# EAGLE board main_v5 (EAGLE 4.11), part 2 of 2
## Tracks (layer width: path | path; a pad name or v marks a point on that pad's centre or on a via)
+5V  (via drill 0.61)
  Top 0.61: IC501.16 144.14,18.89 145.41,20.16 145.41,25.87 149.22,29.68 149.22,33.49 149.85,34.12 IC501.9 | 97.15,52.54 IC402.16 104.77,52.54 106.36,50.95 115.25,50.95 116.83,52.54 IC403.16 | IC301.14 146.68,133.19 153.03,139.53 153.03,143.34 | 153.03,143.34 153.03,147.16 154.3,148.42 R304.2 | 153.03,143.34 R305.2 | Q802.3 168.91,32.7 168.91,27.93 Q801.3
  Top 0.813: C306.1 100.32,121.76 97.15,117.95 97.15,52.54 v97.15,35.08
  Bottom 0.61: IC501.16 C508.1 R501.2 139.69,22.7 140.97,23.96 140.97,27.14 141.6,27.78 144.78,27.78 145.41,28.41 145.41,29.68 144.78,30.32 138.42,30.32 137.79,29.68 137.79,24.6 136.52,23.33 136.52,18.25 135.25,16.98 135.25,10.63 133.98,9.36 C506.1 130.17,10 116.44,10 114.3,12.22 114.3,25.87 113.02,27.14 111.12,27.14 109.85,28.41 IC51.6 | R402.2 128.9,42.38 130.17,43.65 130.17,50.25 | 130.17,50.25 R401.1 132.07,53.17 132.07,68.42 130.81,69.69 130.81,75.4 132.07,76.67 132.07,78.58 130.17,80.48 114.93,80.48 114.3,81.12 IC401.14 | 130.17,50.25 123.82,50.25 122.55,51.27 122.55,57.62 121.28,58.89 116.83,58.89 116.2,58.25 116.2,53.17 116.83,52.54 IC403.16 | 152.39,34.12 152.32,34.12 | 152.39,34.12 154.3,34.12 158.27,30.16 167,30.16 168.91,32.06 168.91,32.85 Q802.3 | IC501.9 152.39,34.12
  Bottom 0.813: C703.1 IC702.OUT | 90.8,33.49 R701.2 31.27,33.49 28.57,30.79 C703.1 | 90.8,33.49 95.56,33.49 v97.15,35.08 107.94,35.08 109.85,32.22 IC51.6 | 90.8,33.49 IC1.6 | 103.5,122.39 103.5,122.87 107.31,126.84 120.01,126.84 126.36,120.48 C301.1 134.93,120.48 136.49,122.04 142.84,122.04 144.14,123.34 IC301.4 | IC301.4 144.14,124.45 | IC301.4 144.14,126.2 146.68,128.74 IC301.14 | C704.1 22.22,23.96 24.76,26.5 C703.1 | 103.5,122.39 | 103.5,122.39 C306.1
+15V  (via drill 2.54)
  Bottom 1.016: IC701.IN 60.32,18.89 59.05,17.62 10.79,17.62 8.25,20.16 8.25,21.43 | 8.25,21.43 8.25,31.59 12.06,35.39 94.61,35.39 97.15,37.93 170.81,37.93 176.53,43.65 L601.1 | v5.71,21.43 8.25,21.43
GND  (via drill 0.25 pad 12.7, 0.61, 2.54)
  Top 0.61: 37.46,150.97 VR251.2 36.19,139.53 36.19,116.67 | 12.06,150.97 VR201.2 10.79,139.53 10.79,116.67 | 10.79,116.67 VR202.2 | 10.79,116.67 10.79,106.52 | 10.79,106.52 VR202.3 | 10.79,106.52 R208.1 | 36.19,116.67 36.83,116.67 36.83,106.52 | 36.83,106.52 VR252.3 | 36.83,106.52 36.83,103.34 R258.1 36.83,102.07 36.83,90.32 | 36.19,116.67 VR252.2 | C255.2 C256.2 | C205.2 C206.2 | 36.83,90.32 34.29,90.32 33.02,89.05 33.02,72.86 31.11,70.95 | CON1.6 CON1.5 | 97.15,23.33 R1.1 | IC1.3 IC1.4 | 31.11,70.95 C208.2 | C208.2 C210.2 26.98,56.35 26.98,51.27 28.89,49.36 R218.1 | C208.2 32.38,60.79 34.92,58.25 C261.2 44.13,52.86 47.3,52.86 | C258.2 C260.2 52.7,55.71 52.7,49.36 | 52.7,49.36 R268.1 | 52.7,49.36 52.7,50.16 52.54,50.32 49.84,50.32 47.3,52.86 | 140.63,88.73 arc-45 141.2,88.5 141.6,88.1 | 141.6,88.1 C405.2 | C406.2 141.2,93.42 arc45 140.97,92.84 140.97,88.73 141.6,88.1 | 116.2,23.33 R51.1 | 36.83,90.32 IC203.GND | v82.23,30 82.23,33.81 83.5,35.08 v83.5,38.25 80.64,38.25 | 65.4,87.47 IC253.GND | IC201.4 28.57,73.5 31.11,70.95 | C224.2 13.97,56.35 C211.2 | 47.3,52.86 46.98,52.86 C274.2 | C53.2 123.19,23.33 | 123.19,19.52 R52.1 | 93.37,1.1 93.37,4.98 | 107.31,1.1 107.31,1.74 | 107.31,1.74 107.31,1.77 | 117.47,1.1 R53.1 | 173.35,17.62 C801.2 | 163.98,34.12 C511.2 | U$8.P$2 165.73,6.19 | C512.2 153.66,36.03 153.66,37.93 | 107.31,1.74 VR51.1 | 128.27,139.53 128.11,139.53 X301.5
  Top 0.813: 207.64,48.09 C616.2 201.92,46.19 194.31,46.19 C617.2 | 207.64,48.09 207.64,39.2 | 207.64,39.2 207.64,25.23 | 207.64,25.23 207.64,21.43 | 207.64,21.43 207.64,17.62 | 207.64,17.62 207.64,13.8 | 207.64,13.8 207.64,1.1 194.94,1.1 | 194.94,1.1 173.35,1.1 | 173.35,1.1 173.35,6.82 | 173.35,6.82 173.35,16.34 | 173.35,29.05 173.35,34.12 | 173.35,29.05 173.35,17.62 173.35,16.34 | 173.35,34.12 173.35,37.93 | 173.35,37.93 173.35,43.01 180.97,43.01 | 180.97,43.01 C619.2 | 173.35,37.93 C614.2 | 173.35,34.12 C613.2 | 173.35,16.34 C615.2 | 173.35,6.82 R604.1 | 194.94,1.1 R602.1 | 207.64,13.8 C601.2 | 207.64,17.62 C602.2 | 207.64,21.43 R603.1 | 207.64,25.23 C604.2 | 203.19,39.2 R608.1 | 207.64,39.2 203.19,39.2 | 203.19,39.2 C607.2 | R609.1 173.35,77.31 173.35,79.84 | 173.35,90.64 173.35,88.42 | 173.35,88.42 173.35,83.66 | 173.35,83.66 173.35,79.84 | 191.13,150.97 190.5,150.97 | 191.13,150.97 207.64,150.97 207.64,93.81 | 207.64,93.81 207.64,83.66 | 207.64,83.66 207.64,81.75 | 207.64,81.75 207.64,77.31 | 207.64,77.31 207.64,48.09 | 207.64,77.31 TR601SEC.2 | 173.35,90.64 C618.2 | 173.35,88.42 T603.2 187.95,88.73 | 173.35,79.84 183.51,79.84 D601.1 207.64,81.75 | 187.95,88.73 187.95,93.81 207.64,93.81 | 187.95,88.73 187.95,83.66 | 207.64,83.66 187.95,83.66 | 187.95,83.66 173.35,83.66 | 163.98,16.34 163.98,18.81 | 163.98,13.8 163.98,16.34 | 163.98,13.8 R502.2 | 163.98,18.81 C509.2 159.47,18.79 157.47,20.79 C510.2 | 163.98,16.34 C507.2 | 163.98,9.36 163.98,10.83 | 163.98,10.83 163.98,13.8 | 142.87,1.1 130.81,1.1 | 153.03,1.1 142.87,1.1 | 160.65,1.1 153.03,1.1 | 130.81,1.1 C506.2 | 125.09,16.98 C501.1 | 125.09,1.1 130.81,1.1 | 125.09,16.98 125.09,18.89 | 125.09,18.89 C508.2 136.52,16.98 140.33,16.98 141.41,18.25 141.41,20.79 142.23,21.43 IC501.15
  Top 0.813: 125.09,18.89 125.09,25.23 | 125.09,25.23 125.09,29.05 | 125.09,29.05 C502.1 | 125.09,25.23 C504.2 | 163.98,9.36 160.65,9.36 CON1.19 CON1.20 160.65,1.1 | 153.03,1.1 CON1.14 CON1.13 | 142.87,1.1 CON1.6 | 173.35,1.1 165.73,1.1 | 165.73,1.1 160.65,1.1 | 173.35,29.05 IC601.GND | 179.7,150.97 191.13,150.97 | 179.7,150.97 179.06,150.97 | 173.35,150.97 173.35,136.99 | 173.35,136.99 173.35,133.19 | 173.35,133.19 173.35,121.76 | 173.35,150.97 179.7,150.97 | 163.19,150.97 173.35,150.97 | 163.19,150.97 163.19,145.88 | 163.19,145.88 163.19,140.8 | 163.19,140.8 163.19,110.96 142.71,110.96 | 163.19,145.88 ZD302.A | 163.19,140.8 ZD301.A | 142.71,110.96 130.17,110.96 | 130.17,110.96 116.2,110.96 | 116.2,110.96 107.31,110.96 | 107.31,110.96 103.5,110.96 C306.2 | 128.11,150.97 104.77,150.97 | 128.11,150.97 163.19,150.97 | 116.2,110.96 L301.1 | 107.31,110.96 C305.1 | VR301.1 104.77,124.3 104.77,150.97 | 123.19,1.1 125.09,1.1 | 123.19,1.1 117.47,1.1 107.31,1.1 93.37,1.1 83.19,1.1 | 80.64,1.1 83.19,1.1 | 80.64,1.1 80,1.1 | C3.2 97.15,23.33 IC1.4 IC1.3 90.8,21.43 90.16,20.79 C5.2 | C3.2 R2.1 | 83.19,1.1 VR1.1 | C3.2 100.96,24.6 102.23,25.87 108.58,25.87 109.85,24.6 IC51.3 | 163.98,18.81 163.98,34.12 163.98,37.93 153.66,37.93 130.25,37.93 130.25,39.84 143.5,39.84 | 163.19,74.13 163.19,109.06 144.14,109.06 | 163.19,61.43 163.19,74.13 | 163.19,53.81 163.19,61.43 | 163.19,53.81 163.19,39.84 143.5,39.84 | 125.09,29.05 125.09,35.39 126.36,35.39 126.36,37.36 98.42,37.36 | 0.63,16.34 v5.71,16.34 | 0.63,16.34 0.63,1.1 76.19,1.1 | 60.32,35.39 76.19,35.39 76.19,19.52 78.1,19.52 78.1,35.39 80.64,35.39 80.64,37.3 | 33.65,35.39 45.08,35.39 | 0.63,35.39 17.77,35.39
  Top 0.813: 17.77,35.39 18.41,35.39 C704.2 | 0.63,35.39 0.63,16.34 | 76.19,1.1 78.1,1.1 | 78.1,1.1 80.64,1.1 | IC702.GND 31.11,23.33 33.65,25.87 C703.2 33.65,35.39 | 45.08,35.39 C701.2 | 0.63,70.32 0.63,58.25 | 0.63,70.32 0.63,150.97 12.06,150.97 27.3,150.97 | 0.63,70.32 C223.2 | 0.63,58.25 C211.2 | 73.02,37.3 61.59,37.3 | 73.02,37.3 73.66,37.3 | 0.63,58.25 0.63,37.3 | 0.63,37.3 0.63,35.39 | 80.64,37.3 73.02,37.3 | 61.59,37.3 C264.2 | 80.64,37.3 80.64,38.25 C222.2 | C266.2 78.1,76.35 IC252.4 78.1,70.95 | 78.1,70.95 C268.2 | C216.2 78.1,53.17 IC202.4 78.1,48.09 | 78.1,48.09 C218.2 | 95.88,85.56 95.88,84.92 | 95.88,85.56 65.4,85.56 65.4,87.47 65.4,93.81 | 65.4,150.97 65.4,93.81 | 104.77,150.97 65.4,150.97 | 144.14,109.06 98.42,109.06 | 98.42,95.72 98.42,90.64 | 98.42,109.06 98.42,95.72 | 65.4,93.81 C273.2 | C272.2 83.5,61.11 87.31,61.11 | 87.31,61.11 95.88,61.11 | IC403.6 IC403.7 IC403.8 125.72,73.5 | R410.1 140.63,88.73 arc-45 141.2,88.5 C405.2 | 144.14,109.06 144.14,99.53 | 144.14,99.53 C406.2 140.97,93.18 140.97,88.73 140.97,84.92 129.53,73.5 125.72,73.5 | IC402.6 IC402.7 IC402.8 110.48,71.59 112.39,73.5 114.3,73.5 | 98.42,90.64 C401.2 | 98.42,95.72 C402.2 | 157.47,53.81 C410.2 | 163.19,53.81 157.47,53.81 | 157.47,53.81 C404.2 | 143.5,39.84 R425.1 | 163.19,74.13 R412.1 | 123.82,73.5 114.3,73.5 | 123.82,73.5 124.12,73.5 | 114.3,73.5 IC401.5 | 144.14,99.53 R422.2 | IC404.4 142.87,65.88 147.31,61.43 163.19,61.43 | 45.08,35.39 54.61,35.39 54.61,37.3 33.65,37.3 | 0.63,37.3 33.65,37.3 | 33.65,37.3 C214.2 33.65,42.06 32.06,43.65 30.47,43.65 29.2,45.24 29.2,49.36 R218.1 | 123.19,1.1 123.19,6.19 125.09,6.19 125.09,1.1 | 125.09,16.98 125.09,10 123.19,10 123.19,19.52 123.19,23.33 123.19,35.39 99.05,35.39 99.05,34.12 98.42,33.49 95.24,33.49 95.24,36.03 95.88,36.66 95.88,37.3 86.99,37.3 86.99,37.93
  Top 0.813: 76.19,1.1 76.19,16.03 78.1,16.03 78.1,1.1 | 125.72,73.5 123.82,73.5 | 98.42,90.64 98.42,54.45 | 61.59,37.3 58.41,37.3 58.41,35.39 60.32,35.39 | IC51.3 IC51.4 116.2,23.33 C53.2 | C55.2 109.21,20.79 109.85,21.43 IC51.3 | 65.4,150.97 52.7,150.97 | 52.7,150.97 37.46,150.97 27.3,150.97 | 27.3,150.97 LEFT.2@2 | 52.7,150.97 RIGHT.2@2 | 17.77,35.39 33.65,35.39 | IC701.GND 57.78,23.33 60.32,25.87 C702.2 60.32,35.39 | 87.31,61.11 87.31,68.1 85.72,69.69 83.18,69.69 81.91,70.95 78.1,70.95 | 86.99,37.93 86.99,44.92 84.45,47.46 82.55,47.46 81.91,48.09 78.1,48.09 | 86.99,37.93 86.99,37.62 | 173.35,121.76 C611.2 | 173.35,121.76 173.35,110.33 | 173.35,110.33 173.35,105.88 | 173.35,133.19 C612.2 | 173.35,105.88 173.35,90.64 | 130.17,110.96 C301.2 | IC301.5 146.68,123.18 145.73,122.23 142.71,122.23 | 142.71,122.23 139.85,122.23 139.22,122.87 | 139.22,122.87 | 139.22,122.87 139.06,123.03 IC301.2 | 142.71,110.96 142.71,122.23 | 128.11,150.97 128.11,139.53 128.11,138.74 122.55,133.19 C302.2 | 163.98,9.36 163.98,6.19 165.73,6.19 165.73,1.1 | 95.88,85.56 95.88,117.95 | 98.42,109.06 98.42,116.67 | K1.6 178.43,63.33 188.59,63.33 188.59,56.98 184.78,53.17 184.78,43.01 180.97,43.01 | C6.2 | 163.98,10.83 C6.2 | 175.76,110.33 175.89,110.33 | 175.76,110.33 C610.2 | 173.35,110.33 175.76,110.33 | 175.89,105.88 C609.- 173.35,105.88 | 182.18,136.99 182.24,136.99 | 182.18,136.99 U$6.P$4 | 173.35,136.99 182.18,136.99
  Bottom 0.61: VR201.2 6.34,136.36 C223.2 6.34,44.92 13.01,38.25 v83.5,38.25 | v82.23,30 82.23,11.76 89.07,4.92 92.09,4.92 R3.1 | IC251.4 53.97,75.4 59.69,80.8 59.69,86.83 60.32,87.47 IC253.GND | C303.2 C302.2 | 150.62,0.85 188.97,0.85 193.29,5.04 194.94,5.04 R602.1
  other vias: 200.4,88.73
  pour Top (isolate 0.61): 0.63,1.1 207.64,1.1 207.64,150.97 0.63,150.97
  pour Bottom (isolate 0.61): 0.63,151.6 207,151.6 207,0.47 0.63,0.47
IC402
  Bottom 0.61: R277.2 73.02,81.12 IC252.7 IC252.6 75.56,82.7 77.46,84.61 93.02,84.61 97.78,79.84 97.78,67.15 100.96,63.97 104.13,63.97 104.77,63.33 104.77,60.79 104.13,60.16 IC402.13 100.32,60.16 100.32,44.92 101.02,43.9 104.2,43.9 107.31,40.86 111.12,40.86 112.01,41.74 112.01,43.08 111.12,44.03 109.79,44.03 108.58,45.24 108.58,51.9 109.21,52.54 | 109.21,52.54 112.39,53.81 112.39,57.4 | 112.39,57.4 IC402.3 | IC402.3 | 112.39,57.4 113.56,57.4 116.3,60.16 IC403.13 121.91,60.16 124.45,57.62 IC403.3 126.99,57.62 127.63,56.98 127.63,53.17 126.99,52.54 IC403.1 | 109.21,52.54 IC402.1
N$1
  Top 0.61: R420.2 146.04,65.24 148.59,62.7 152.39,62.7 153.35,63.97 153.35,65.24 152.39,66.51 151.76,66.51 147.95,70.32 145.41,70.32 144.14,71.59 C405.1
  Bottom 0.61: IC404.3 138.42,67.15 139.06,67.78 145.41,67.78 146.04,67.15 R420.2
N$2
  Bottom 0.61: JP201.2 C201.1
N$3
  Bottom 0.61: C202.1 27.3,136.99 C201.2 R201.2
N$4
  Bottom 0.61: R202.1 R203.1 27.3,130.64 C202.2
N$5
  Bottom 0.61: 28.57,120.48 R204.1 22.22,120.48 T201.2 | 28.57,120.48 R203.2 | 28.57,120.48 C204.1
N$6
  Bottom 0.61: R3.2 88.89,12.54 88.26,13.17 | 88.26,13.17 IC1.2 | VR1.3 88.26,13.17
N$7
  Bottom 0.61: VR203.2 12.06,100.17 19.68,106.52 19.68,109.06 20.95,110.33 23.49,110.33 24.76,109.06 T202.E
N$8
  Bottom 0.61: VR202.1 R205.1
N$9
  Bottom 0.61: C203.1 R204.2
N$10
  Bottom 0.61: C203.2 19.68,123.03 R206.1 T201.3
N$11
  Top 0.61: C206.1 31.11,112.23 29.84,113.5 24.7,113.5 | 24.7,113.5 24.73,114.9 16.38,114.9 15.24,116.04 15.24,125.88 R206.2 | 24.7,113.5 24.76,113.5 C205.1
  Bottom 0.61: R206.2 R205.2 | T202.C 30.47,106.52 31.11,107.15 C206.1
N$12
  Bottom 0.61: R207.1 C204.2
N$13
  Bottom 0.61: 22.22,105.25 22.22,103.98 23.49,102.7 VR204.2 26.03,102.7 27.3,103.98 T202.B | 22.22,105.25 22.22,105.88 | 22.22,105.25 C207.2
N$14
  Top 0.61: VR204.1 28.57,102.7 27.3,101.44 VR204.3 19.68,92.55 17.14,90.01 17.14,74.77 14.6,72.23 VR205.3
N$15
  Bottom 0.61: IC201.5 27.3,82.39 25.71,83.97 25.71,87.78 26.66,88.73 R209.1
N$16
  Bottom 0.61: R210.2 28.57,83.66 R211.1 R212.2 31.11,80.16 30.16,79.21 22.86,79.21 22.22,79.84 IC201.7
N$17
  Bottom 0.61: R211.2 30.47,90.64 24.12,90.64 LED201.A LED202.K 16.5,76.67 25.39,76.67 26.03,76.04 26.03,72.23 27.3,70.95 VR206.1
N$18
  Bottom 0.61: VR206.3 26.03,63.33 R214.1
N$19
  Bottom 0.61: VR205.2 12.06,69.05 13.33,67.78 27.3,67.78 31.11,70.95 R212.1
N$20
  Top 0.61: 22.86,84.92 22.86,88.73 24.76,90.64 27.93,90.64 33.65,96.36 R207.2 | 22.86,84.92 R210.1 | 22.86,84.92 24.76,83.02 IC201.6
N$21
  Bottom 0.61: R213.1 13.33,74.77 VR205.1
N$22
  Bottom 0.61: 19.68,48.09 C213.2 | C212.2 19.68,46.82 19.68,48.09 | 19.68,48.09 R218.2
N$23
  Bottom 0.61: R215.1 33.65,60.79 | 33.65,60.79 R214.2 | 33.65,60.79 C208.1
N$24
  Bottom 0.61: R216.1 29.84,51.9 C209.1 31.11,51.9 R215.2
N$25
  Top 0.61: R216.2 22.22,55.08 23.49,56.35 C210.1 23.49,63.33 26.03,65.88 26.03,70.95 24.76,72.54 IC201.3
N$26
  Bottom 0.61: C211.1 15.87,58.25 12.06,54.45 R217.2 10.79,51.43 9.52,50.16 C212.1
N$27
  Bottom 0.61: C252.2 52.7,130.64 R253.1 R252.1
N$28
  Bottom 0.61: C209.2 20.31,51.9 18.41,53.81 R217.1 18.41,56.98 18.73,57.3 18.73,59.52 15.55,62.7 12.06,62.7 10.16,64.61 10.16,71.59 11.43,72.86 12.7,72.86 13.97,71.59 13.97,69.69 14.6,69.05 17.77,69.05 19.68,70.95 IC201.1 IC201.2
N$29
  Bottom 0.61: 47.62,46.82 R268.2 | 47.62,46.82 C263.2 | C262.2 47.62,46.82
N$30
  Bottom 0.61: R251.2 C251.2 52.7,136.99 C252.1
N$31
  Bottom 0.61: JP251.2 C251.1
N$32
  Bottom 0.61: VR251.3 JP251.1 48.89,131.91 50.16,133.19 53.97,133.19 R251.1
N$33
  Bottom 0.61: VR253.2 38.73,100.17 45.08,106.52 45.08,109.06 46.35,110.33 48.89,110.33 51.43,107.79 T252.E
N$34
  Bottom 0.61: 53.97,120.48 R253.2 | 53.97,120.48 R254.1 47.62,120.48 T251.2 | 53.97,120.48 C254.1
N$35
  Bottom 0.61: C253.1 R254.2
N$36
  Bottom 0.61: C253.2 45.08,123.03 R256.2 T251.3
N$37
  Top 0.61: C256.1 56.51,112.23 55.11,113.59 50.16,113.59 50.16,114.77 | 50.16,114.77 41.67,114.79 40.64,115.84 40.64,125.88 R256.1 | 50.16,114.77 C255.1
  Bottom 0.61: R256.1 R255.2 | C256.1 T252.C
N$38
  Bottom 0.61: VR252.1 R255.1
N$39  (via drill 0.61)
  Top 0.61: v83.5,31.27 83.5,33.49 84.77,34.76 v84.77,39.52
  Bottom 0.61: VR51.2 104.87,10.55 85.52,10.54 83.5,12.56 v83.5,31.27 | C51.2 19.04,147.16 17.14,149.06 15.24,149.06 14.6,148.42 14.6,142.07 7.62,135.09 7.62,45.55 13.65,39.52 v84.77,39.52
N$40
  Bottom 0.61: C257.2 47.62,105.25 50.16,102.7 VR254.2 52.7,102.7 53.97,103.98 T252.B
N$41
  Bottom 0.61: R257.1 C254.2
N$42
  Bottom 0.61: IC251.5 53.97,82.39 52.07,84.29 52.07,87.47 53.34,88.73 R259.1
N$43
  Top 0.61: 49.53,84.92 49.53,88.73 51.43,90.64 54.61,90.64 59.05,95.09 R257.2 | 49.53,84.92 R260.1 | 49.53,84.92 51.43,83.02 IC251.6
N$44
  Bottom 0.61: R261.2 57.15,90.64 50.8,90.64 LED251.A LED252.K 41.91,78.58 43.81,76.67 51.43,76.67 52.7,75.4 52.7,72.23 53.97,70.95 VR256.1
N$45
  Bottom 0.61: R260.2 55.24,83.66 R261.1 R262.2 55.56,78.89 50.16,78.89 48.89,80.16 IC251.7
N$46
  Bottom 0.61: VR256.3 52.7,62.7 R264.1
N$47
  Bottom 0.61: R265.1 60.32,60.79 R264.2
  Bottom 0.813: 60.32,60.79 C258.1
N$48
  Bottom 0.61: R265.2 57.78,51.9 C259.1 56.51,51.9 R266.1
N$49
  Bottom 0.61: VR255.2 38.73,69.69 40.64,67.78 53.97,67.78 57.78,70.95 R262.1
N$50
  Top 0.61: VR254.1 55.24,102.7 53.97,101.44 VR254.3 46.98,92.55 44.45,90.01 44.45,84.54 45.72,83.27 46.98,83.27 47.62,82.64 47.62,79.84 40.32,72.54 40.32,61.75 VR255.3
N$51
  Bottom 0.61: R263.1 40,74.77 VR255.1
N$52
  Bottom 0.61: RIGHT.1 51.43,143.34 50.16,144.61 42.54,144.61 VR251.1 42.54,146.52 41.91,147.16 C51.1
N$53
  Top 0.61: R266.2 48.89,55.71 50.16,56.98 C260.1 50.16,63.33 52.7,65.88 52.7,70.95 51.43,72.23 IC251.3
N$54
  Bottom 0.61: C259.2 46.98,51.9 45.08,53.81 R267.1 45.08,56.98 46.35,58.25 46.35,59.52 43.18,62.7 40,62.7 36.83,65.88 36.83,71.59 38.1,72.86 39.37,72.86 40.64,71.59 40.64,69.69 41.27,69.05 44.45,69.05 46.35,70.95 IC251.1 IC251.2
N$55
  Bottom 0.61: C261.1 40,54.45 R267.2 C262.1
N$56
  Top 0.61: C274.1 46.98,63.65 50.16,66.83 VR256.2
  Bottom 0.61: 47.62,114.14 55.24,114.14 56.51,115.41 56.51,117.95 R252.2 61.59,117.95 61.59,98.9 | 47.62,114.14 T251.1 | 45.08,98.9 VR253.1 | 45.08,98.9 45.08,100.8 | 45.08,100.8 45.08,101.44 | 47.62,114.14 C257.1 | 45.08,88.73 45.08,98.9 | 45.08,88.73 R259.2 | 45.08,88.73 VR253.3 LED251.K 38.1,84.92 36.19,83.02 R263.2 36.19,79.84 39.68,76.04 LED252.A 42.54,76.04 43.18,75.4 49.53,75.4 50.16,74.77 VR256.2 | 45.08,98.9 61.59,98.9 | 61.59,98.9 C273.1 IC253.OUT | 45.08,100.8 R258.2
N$57
  Bottom 0.61: VR201.3 JP201.1 23.49,131.91 24.12,132.55 29.2,132.55 R201.1
N$58
  Top 0.61: VR51.3 116.83,13.17 R53.2
  Bottom 0.61: VR51.3 108.58,13.17 107.31,14.44 IC51.2
N$59
  Bottom 0.61: 17.14,144.61 24.76,144.61 LEFT.1 | VR201.1 17.14,144.61 | 17.14,144.61 17.14,145.88 C1.1
N$60
  Bottom 0.61: C52.1 104.77,21.11 IC51.1
N$61
  Bottom 0.61: C52.2 105.41,18.25 106.04,18.89 106.04,27.78 104.77,29.05 IC51.8
N$62
  Bottom 0.61: 118.1,29.68 R51.2 | C54.2 118.1,30.95 118.1,29.68 | D51.A 118.74,15.71 118.1,16.34 118.1,29.68
N$63
  Bottom 0.61: CON1.7 144.14,7.46 128.9,7.46 127.63,8.72 114.93,8.72 112.39,11.27 112.39,13.8 D51.C 109.85,18.25 | C55.1 109.85,18.25 | 109.85,18.25 111.75,18.25 112.39,18.89 R52.2
N$64  (via drill 0.61)
  Top 0.61: v80.96,28.73 80.96,34.12 82.23,35.39 v82.23,36.98
  Bottom 0.61: VR1.2 88.27,3.59 80.96,10.9 v80.96,28.73 | C1.2 9.52,143.34 9.52,142.07 5.08,137.63 5.08,44.28 12.38,36.98 v82.23,36.98
N$65
  Bottom 0.813: R601.2 175.89,11.9 175.89,19.52 L602.2 177.79,21.43 IC601.OUT 178.43,27.78 179.7,29.05 179.7,33.49 C613.1 179.7,34.76 179.7,36.66 C614.1
N$66
  Bottom 0.813: 196.84,16.34 R602.2 192.4,11.9 189.22,11.9 187.95,13.17 185.41,13.17 184.14,11.9 R601.1 | 196.84,16.34 C602.1 | 196.84,16.34 C601.1 | T601.B 194.31,18.89 196.84,16.34
N$67
  Bottom 0.813: C605.1 L602.1 | L602.1 T601.C | L602.1 186.69,22.7 186.05,23.33 183.51,23.33 182.88,23.96 C603.1
N$68
  Bottom 0.813: C603.2 189.22,26.5 191.76,23.96 | 191.76,23.96 T601.E 191.76,15.71 R605.2 | 191.76,23.96 C606.2 196.84,23.96 | 196.84,23.96 C604.1 | 196.84,23.96 R603.2
N$69
  Bottom 0.61: R604.2 184.14,8.72 184.19,8.77 | 184.19,8.77 C605.2 | 184.19,8.77 173.43,8.77 170.81,6.14 170.81,6.19 170.82,6.18 U$7.P$2
N$70
  Top 0.813: 193.03,30.32 C606.1 | R606.1 187.95,30.32 193.03,30.32 | 193.03,30.32 T602.2
N$71
  Top 0.813: R607.1 194.94,38.57 193.11,38.57 T602.4
  Bottom 0.813: R607.1 200.02,43.65 200.02,48.73 201.29,50 202.56,50 203.19,50.63 TR601PRI.2
N$72
  Bottom 0.61: C6.1 159.62,8.13 161.48,8.13 167.48,2.06 188.3,2.06 190.5,4.28 R605.1 | C6.1 154.89,10.83 C513.2 | C6.1 | C6.1 156.92,10.79
N$73
  Top 0.813: 199.38,32.85 C607.1 | 195.57,32.85 199.38,32.85 | 199.38,32.85 R608.2 | 195.57,32.85 195.57,34.12 190.5,34.12 190.5,32.52 T602.1 | T602.3 195.57,32.52 195.57,32.85
N$74
  Bottom 0.813: 189.22,77.31 TR601SEC.1 | R609.2 189.22,77.31 | T603.1 187.32,91.28 189.22,89.37 189.22,77.31
N$75
  Bottom 0.61: CON1.8 144.14,4.92 134.62,4.92 133.34,6.25 127.57,6.25 126.36,7.46 111.04,7.53 111.06,7.52 104.94,13.55 104.77,13.55 96.01,13.54 93.97,15.7 93.97,15.71 D1.C 90.8,18.25 | 90.8,18.25 C5.1 | 90.8,18.25 92.07,18.25 R2.2
N$76
  Bottom 0.813: L603.2 186.37,70.95 184.78,69.37 182.24,69.37 180.34,71.27 180.34,86.2 | 180.34,86.2 C608.1 | 180.34,86.2 T603.3
N$77
  Bottom 0.813: C608.2 L604.1
N$78
  Bottom 0.61: R301.1 138.42,146.84 124.14,146.84 121.18,143.88 X301.7
N$79
  Bottom 0.813: 184.78,121.76 L606.1 | 184.78,121.76 L605.2 | C611.1 184.78,121.76
N$80
  Bottom 0.813: C612.1 L606.2 184.78,136.99 184.72,136.99 U$6.P$3
N$81
  Bottom 0.61: R303.1 139.69,141.12 136.52,144.3 126.04,144.3 125.28,143.53 125.28,139.72 125.09,139.53 X301.4
N$82
  Bottom 0.813: C610.1 180.84,110.33 L605.1 L604.2 C609.+
N$83
  Bottom 0.61: C503.1 134.62,25.23 C504.1 128.27,21.43 R504.1
N$84
  Bottom 0.61: 178.43,73.5 K1.1
  Bottom 0.813: 189.22,51.9 C617.1 | 189.22,51.9 L601.2 181.92,53.49 178.43,56.98 178.43,73.5 178.43,81.75 | 189.22,51.9 TR601PRI.1 196.21,51.9 196.84,51.27 C616.1 | C617.1 C619.1 | C617.1 189.22,43.01 | 189.22,43.01 189.22,41.74 R606.2 183.51,36.03 183.51,30 180.97,27.46 180.97,23.33 182.88,21.43 C615.1 | 189.22,43.01 R607.2 | 178.43,81.75 C618.1 | D601.2 178.43,81.75
N$85
  Bottom 0.61: C501.2 128.9,11.9 131.44,14.44 Q501.1
N$86
  Bottom 0.61: IC501.17 140.33,16.34 138.42,14.44 Q501.2
N$87
  Bottom 0.61: CON1.15 154.3,7.46 147.57,7.46 145.41,9.61 145.41,23.33 144.78,23.96 IC501.14
N$88
  Bottom 0.61: CON1.17 158.11,7.2 156.84,8.47 153.39,8.47 | 153.39,8.47 148.08,8.47 146.36,10.12 146.36,25.49 145.41,26.5 IC501.13 | Q801.2 165.65,26.5 163.98,24.84 163.98,18.49 160.25,14.76 156.68,14.76 153.35,11.4 153.36,11.41 153.36,9.74 153.36,8.49 153.39,8.49 153.39,8.47
N$89
  Bottom 0.61: IC501.12 140.08,29.05 139.69,28.66 R501.1 139.69,24.6 137.79,22.7 137.79,17.62 136.52,16.34 136.52,10.63 138.42,8.72 144.78,8.72 146.68,6.82 146.68,5.55 147.31,4.92 156.84,4.92 CON1.18
N$90
  Bottom 0.61: IC1.5 95.88,30.95 98.42,33.81 100.96,33.81 C4.1 102.23,29.05 101.59,28.41 C3.1
N$91
  Bottom 0.61: 99.05,29.68 R1.2 | C4.2 99.05,30.95 99.05,29.68 | D1.A 99.69,15.71 99.05,16.34 99.05,29.68
N$92
  Bottom 0.61: R302.1 137.47,145.57 125.41,145.57 123.91,144.07 123.91,142.17 123.82,142.07 X301.8
N$93
  Bottom 0.61: C502.2 130.81,30.95 133.98,34.12 IC501.10
N$94
  Top 0.61: C411.2 130.17,43.01 128.9,41.74 128.9,36.66 146.04,36.66 147.95,34.76 147.95,30.32 147.31,29.68 146.04,29.68 145.41,30.32 145.41,32.22 144.78,32.85 137.79,32.85 135.25,30.32 C503.2
  Bottom 0.61: C412.1 154.3,43.01 153.66,42.38 R425.2 147.95,42.38 146.04,44.28 138.42,44.28 137.16,43.01 C411.2
N$95
  Top 0.61: IC301.6 149.22,126.84 147.95,128.1 145.41,128.1 142.87,130.64 142.87,133.19 141.6,134.45 141.6,143.34 144.14,145.88 ZD302.C
  Bottom 0.61: 148.59,148.42 R301.2 | 148.59,148.42 R304.1 | ZD302.C 148.59,148.42
N$96
  Bottom 0.61: C2.2 86.35,18.25 86.99,18.89 86.99,27.78 85.72,29.05 IC1.8
N$97
  Bottom 0.61: R302.2 R305.1 150.49,143.34 151.12,142.71 151.12,136.36 151.76,135.72 | 151.76,135.72 D301.A | IC301.7 151.76,127.47 153.03,128.74 153.03,133.19 151.76,134.45 151.76,135.72
N$98
  Bottom 0.61: IC501.1 R502.1
N$99
  Bottom 0.61: C2.1 85.4,21.11 85.72,21.43 IC1.1
N$100
  Top 0.61: C223.1 11.43,72.86 11.43,80.48 R213.2 | C224.1 20.31,63.65 23.49,66.83 VR206.2
  Bottom 0.61: 22.22,114.14 29.84,114.14 31.11,115.41 31.11,117.95 R202.2 35.55,117.31 35.55,98.9 | 18.41,98.9 VR203.1 | 22.22,114.14 T201.1 | 22.22,114.14 C207.1 | 18.41,98.9 35.55,98.9 | 18.41,88.73 18.41,98.9 | 18.41,88.73 R209.2 | 18.41,88.73 VR203.3 LED201.K 11.43,84.92 9.52,83.02 R213.2 9.52,79.84 12.7,76.04 LED202.A 15.24,76.04 15.87,75.4 22.86,75.4 23.49,74.77 VR206.2 | 35.55,98.9 35.55,89.37 IC203.OUT | 18.41,98.9 R208.2
N$101
  Bottom 0.61: D301.C 143.5,136.36 145.41,138.26 R303.2 147.31,138.9 148.59,140.17 ZD301.C
N$102
  Bottom 0.61: IC301.15 144.14,130.64 140.33,126.84 131.44,126.84 | 131.44,126.84 C303.1 | Q301.1 131.44,126.84
N$103
  Bottom 0.61: IC301.16 141.6,130.64 140.33,129.38 135.25,129.38 132.71,131.91 131.44,131.91 | C302.1 131.44,131.91 | 131.44,131.91 Q301.2
N$104
  Bottom 0.61: R306.1 149.22,121.76 147.95,123.03 147.95,127.63 149.22,128.9 IC301.13
N$105
  Bottom 0.61: R307.1 153.03,126.84 154.3,128.1 IC301.11
N$106
  Top 0.61: R270.2 48.57,38.89 40.95,38.89 38.73,41.11 R701.1
  Bottom 0.61: R701.1 36.51,41.74 34.92,43.33 32.06,43.33 31.11,42.38 R220.2
N$107
  Bottom 0.61: IC301.12 151.76,129.38 150.49,128.1 150.49,121.6 150.93,121.15 150.94,119.85 150.27,119.06 148.33,119.06 147.22,120.17 147.22,120.77 146.04,121.91 144.78,121.91 143.82,120.96 143.82,118.26 R309.1
N$108
  Bottom 0.61: R310.1 158.11,121.76 158.11,127.31 156.84,128.58 IC301.10
N$109
  Bottom 0.61: R308.1 147.31,114.77 153.35,114.77 155.44,116.87 155.44,121.63 156.84,123.03 IC301.9
N$110
  Bottom 0.61: 147.79,118.1 152.71,118.1 154.46,119.85 154.46,122.71 154.3,123.03 IC301.8 | 147.79,118.1 | 147.79,118.1 147.16,118.1 145.41,119.85 R311.1
N$111
  Bottom 0.61: R310.2 R307.2 R306.2 147.31,110.96 139.69,110.96 R308.2 R309.2 137.79,117.95 | C304.1 113.98,121.76 115.25,123.03 117.15,123.03 122.23,117.95 137.79,117.95 | 137.79,117.95 R311.2
N$112
  Bottom 0.61: C305.2 108.58,121.76 111.12,119.22 | 111.12,119.22 116.2,119.22 | 116.2,119.22 117.95,119.22 121.91,115.25 R312.1 | C304.2 111.12,119.22 | 116.2,119.22 L301.2
N$113
  Bottom 0.61: VR301.2 117.79,124.3 120.33,121.76 R312.2
N$114
  Bottom 0.61: IC501.2 C507.1
N$115
  Bottom 0.61: IC501.3 154.49,18.89 154.84,18.63 C509.1
N$116
  Bottom 0.61: IC501.4 154.46,21.43 C510.1 | C510.1
N$117
  Bottom 0.61: IC501.5 152.39,23.96 153.03,23.33 159.38,23.33 C505.2
N$118
  Bottom 0.61: R503.1 161.92,27.78 162.81,27.14 162.81,23.01 C505.1
N$119
  Bottom 0.61: 153.66,26.5 IC501.6 | 153.66,26.5 R503.2 | R506.2 153.66,26.5
N$120  (via drill 0.61)
  Top 0.61: R507.1 154.94,31.59 156.84,29.68 156.84,23.33 156.2,22.7 156.2,19.36 158.04,17.57 158.03,13.77 159.26,12.54 159.38,12.41 162.4,12.41 v162.53,12.54 | v162.53,12.54 162.56,12.54 | v162.53,12.54
  Bottom 0.61: R507.1 152.39,32.85 137.79,32.85 136.52,31.59 136.52,25.23 134.62,23.33 R504.2 | v162.53,12.54 163.19,12.54 164.46,12.54 165.73,11.27 | 165.73,11.27 170.85,11.27 170.85,11.23 | U$8.P$1 165.73,11.22 165.73,11.27 | 170.85,11.23 U$7.P$1 | 170.85,11.23 170.85,11.22
N$121  (via drill 0.61)
  Top 0.61: v128.9,63.97 130.17,63.97 132.07,62.06 132.07,50.63 128.9,47.46 128.9,46.19 126.68,43.9 118.99,43.9 118.1,43.01 R402.1
  Bottom 0.61: 105.09,70.32 109.21,74.13 IC401.3 | 105.09,70.32 IC402.9 | 105.09,70.32 105.09,65.88 107.31,63.97 v128.9,63.97
N$122
  Top 0.61: C513.1 | C513.1 149.19,11.49 149.19,22.03 149.85,22.7 153.66,22.7 155.57,24.6 155.57,29.05 154.43,30.19 152.9,30.19 151.51,31.59 IC501.8
N$123  (via drill 0.61)
  Top 0.61: CON1.16 154.3,4.92 154.3,7.46 153.66,8.09 147.31,8.09 146.04,9.36 146.04,11.27 147.95,12.95 147.95,24.6 v148.59,25.23 | v146.68,30.95 146.68,34.12 145.41,35.39 128.27,35.39 127.63,36.03 127.63,40.22 126.99,40.86 117.47,40.86 116.2,42.06 116.2,45.87 117.41,47.08 126.61,47.08 128.65,49.11 128.65,54.83 130.17,56.35 R401.2
  Bottom 0.61: R401.2 130.17,68.42 123.19,75.4 123.19,78.58 122.55,79.21 112.39,79.21 111.75,78.58 IC401.4 | v148.59,25.23 148.59,28.41 146.68,30.32 v146.68,30.95
N$124
  Bottom 0.61: R407.2 RN401.4 RN402.4 RN402.5
N$125
  Bottom 0.61: R224.1 86.2,49.36 | C219.2 95.24,50 95.24,45.24 94.29,44.28 R223.2 89.53,44.28 | 89.53,44.28 89.53,46.19 R224.1 | 89.53,44.28 C217.1 | R224.1 82.55,53.17 66.67,53.17 L201.2
N$126
  Bottom 0.61: C269.2 95.24,72.86 95.24,69.37 93.66,67.78 R273.2 89.53,67.78 | 89.53,67.78 C267.1 | 89.53,67.78 89.53,69.05 R274.1 82.23,76.35 66.35,76.35 L251.2
N$127
  Bottom 0.61: IC402.4 108.58,60.16 107.31,58.89 107.31,44.6 108.9,42.38 R414.2
N$128
  Bottom 0.61: R415.2 104.77,45.55 106.04,46.82 106.04,56.35 104.77,57.62 IC402.14
N$129
  Bottom 0.61: R416.2 103.82,48.73 104.77,50 104.77,54.45 104.13,55.08 IC402.15
N$130
  Bottom 0.61: IC403.11 115.56,65.24 114.93,65.88 114.93,72.23 116.83,74.13 IC401.6
N$131
  Bottom 0.61: Q801.1 167,25.23 R801.1 C801.1 165.81,17.54
N$132
  Top 0.61: IC402.12 IC402.5
  Bottom 0.61: R227.2 73.02,58.25 IC202.7 IC202.6 75.56,60.48 76.83,61.75 89.85,61.75 90.8,61.11 94.29,61.11 95.88,62.7 IC402.12 | IC402.2 109.53,55.08 108.58,56.03 108.58,58.25 109.21,58.89 111.75,58.89 112.39,59.52 112.39,62.7 | IC403.2 124.45,55.08 123.82,54.45 123.82,51.9 124.45,51.27 127.63,51.27 128.9,52.54 128.9,57.62 127.63,58.89 127.63,62.06 126.99,62.7 IC403.5 IC403.12 112.39,62.7 | IC402.5 112.39,62.7
N$133
  Bottom 0.61: IC403.10 116.83,67.78 116.2,68.42 116.2,71.59 116.83,72.23 118.74,72.23 119.38,72.86 IC401.7
N$134
  Bottom 0.61: IC403.4 125.09,60.16 123.82,61.43 115.25,61.43 R417.2
N$135
  Bottom 0.61: R418.2 120.64,45.55 121.28,46.19 121.28,56.98 120.64,57.62 IC403.14
N$136
  Bottom 0.61: R419.2 119.38,48.73 120.01,49.36 120.01,54.45 119.38,55.08 IC403.15
N$137
  Top 0.61: 75.56,66.51 80.96,66.51 83.5,64.61 C267.2 | IC252.2 73.02,70.64 71.43,69.05 71.43,67.46 72.7,66.51 75.56,66.51 | C265.2 75.56,66.51
  Bottom 0.61: L251.1 65.4,72.23 IC252.1 IC252.2
N$138
  Top 0.406: 66.67,124.3 66.67,140.17 103.5,140.17 103.5,124.3 66.67,124.3
N$139  (via drill 0.61)
  Top 0.61: C406.1 v161.03,91.53
  Bottom 0.61: R414.1 102.86,41.43 104.45,39.84 114.3,39.84 | 112.39,48.73 112.39,50.63 R417.1 | 112.39,45.55 112.39,48.73 | 114.3,42.7 112.39,45.55 | 112.39,48.73 R416.1 | 112.39,45.55 R415.1 | R419.1 R418.1 124.45,45.55 123.82,44.92 123.82,41.11 | 123.82,41.11 123.82,40.47 | 114.3,39.84 114.3,42.7 | 114.3,42.7 C407.2 | C408.2 154.94,105.88 152.39,103.34 152.39,94.45 149.47,91.53 C406.1 | v161.03,91.53 163.19,89.37 163.19,42.38 160.65,39.84 123.82,39.84 | 123.82,39.84 114.3,39.84 | 123.82,39.84 123.82,41.11
N$140
  Bottom 0.61: C263.1 49.21,41.74 50.8,43.33 51.43,43.33 | 51.43,43.33 52.07,43.33 53.65,41.74 R270.1 | 51.43,43.33 R269.1
N$141
  Bottom 0.61: R269.2 60.32,45.55 C264.1 61.59,56.98 | 61.59,56.98 61.53,56.86 | R271.1 65.4,60.79 61.59,56.98
N$142
  Bottom 0.61: C213.1 R220.1 R219.1
N$143  (via drill 0.61)
  Top 0.61: v50.16,47.14 47.3,47.14 43.18,43.01 36.19,43.01 33.65,45.55 | R219.2 33.65,45.55 | 33.65,45.55 C214.1
  Bottom 0.61: R221.1 65.4,42.38 64.13,43.65 56.51,43.65 53.02,47.14 v50.16,47.14
N$144
  Bottom 0.61: R222.1 67.3,43.65 73.02,43.65 | 73.02,43.65 73.34,43.65 C215.1 | 73.02,43.65 R221.2
N$145
  Bottom 0.61: R222.2 73.02,46.19 75.56,48.73 IC202.3 75.56,50.63 76.51,51.59 79.69,51.59 C216.1
N$146
  Bottom 0.61: 73.02,66.51 C265.1 | 73.02,66.51 68.89,66.51 66.99,68.42 R272.1 | 73.02,66.51 R271.2
N$147
  Bottom 0.61: R272.2 75.56,70.95 IC252.3 75.56,73.5 76.83,74.77 79.37,74.77 C266.1
N$148
  Bottom 0.61: C268.1 82.55,67.78 R273.1
N$149
  Bottom 0.61: C218.1 80.96,44.28 R223.1
N$150
  Top 0.61: 75.56,43.65 80.96,43.65 82.86,41.74 C217.2 | C215.2 75.56,43.65 | 75.56,43.65 72.7,43.65 71.43,44.92 71.43,46.19 73.02,47.78 IC202.2
  Bottom 0.61: IC202.2 IC202.1 65.4,49.36 L201.1
N$151
  Bottom 0.61: IC51.5 114.3,30.95 116.2,33.81 120.01,33.81 C54.1 121.28,29.05 120.64,28.41 C53.1
N$152
  Bottom 0.61: IC403.9 120.64,70.32 121.91,71.59 IC401.8
N$153
  Bottom 0.61: C269.1 C270.2 92.07,78.58 R276.1
N$154
  Bottom 0.61: 88.26,82.32 86.35,80.8 R274.2 | 88.26,82.32 C271.2 | R275.1 96.52,65.88 96.52,79.53 93.4,82.32 88.26,82.32
N$155
  Bottom 0.61: IC252.5 78.73,80.48 80.96,80.48 87.94,73.5 C270.1 89.53,72.23 91.44,70.32 93.34,70.32 R275.2
N$156
  Top 0.61: R278.2 83.81,78.58 86.35,76.04 89.85,76.04 92.07,73.81 R276.2
  Bottom 0.61: R277.1 78.73,82.39 C271.1 83.81,81.75 R278.2
N$157
  Bottom 0.61: IC401.9 R403.2
N$158
  Bottom 0.61: 130.17,97.62 RN402.1 | R403.1 130.17,97.62 | 130.17,97.62 130.17,96.36 R410.2
N$159
  Bottom 0.61: C272.1 R278.1
N$161
  Top 0.61: R506.1 160.73,25.23 159.7,26.11 159.7,31.11 159.22,31.59 | 159.22,31.59 C511.1 156.84,34.12 156.84,36.03 C512.1 | 159.22,31.59 R507.2
  Bottom 0.61: R506.1 161.28,21.43 160.05,20.19 148.62,20.19 147.82,19.23 R505.2
N$162
  Bottom 0.61: C222.1 R228.1
N$163
  Bottom 0.61: R224.2 86.35,57.62 C221.2 94.61,59.52 97.15,56.98 97.15,43.97 93.34,40.16 R225.1 93.34,39.2
N$164
  Bottom 0.61: C220.2 92.07,55.71 | 92.07,55.71 R226.1 | 92.07,55.71 C219.1
N$165
  Bottom 0.61: IC202.5 79.05,57.94 80.96,57.94 88.26,50.63 C220.1 89.53,49.36 92.07,46.82 93.34,46.82 R225.2
N$166
  Top 0.61: R228.2 83.81,56.03 86.67,53.17 89.85,53.17 92.07,50.63 R226.2
  Bottom 0.61: R228.2 83.81,58.89 C221.1 78.73,59.52 R227.1
N$167
  Bottom 0.61: IC401.16 109.21,90.64 | 109.21,90.64 C401.1 | 109.21,90.64 Q401.1
N$168
  Bottom 0.61: IC402.11 101.91,65.24 99.05,68.1 99.05,74.45 102.23,77.31 IC401.1
N$169
  Bottom 0.61: IC402.10 101.91,67.78 100.32,69.37 100.32,73.5 102.23,75.4 106.04,75.4 106.67,76.04 IC401.2
N$170
  Bottom 0.61: Q802.2 165.73,33.01 R801.2
N$171
  Bottom 0.61: IC401.15 111.75,93.81 109.85,95.72 | 109.85,95.72 C402.1 | Q401.2 109.34,95.72 109.85,95.72
N$172
  Bottom 0.61: VR401.2 139.69,60.79 137.79,62.7 135.88,62.7 134.62,63.97 134.62,67.78 132.07,70.32 132.07,74.77 134.11,76.77 134.11,89.5 C403.1
N$173
  Bottom 0.61: R408.1 155.57,95.72 154.94,96.36 154.94,102.07 155.57,102.7 158.11,102.7 160.01,104.61 160.01,109.06 | IC401.17 106.67,83.66 106.04,83.02 103.5,83.02 98.17,88.35 98.17,107.15 100.07,109.06 128.27,109.06 130.17,107.15 130.17,105.25 131.44,103.98 138.42,103.98 143.5,109.06 160.01,109.06 | R313.1 157.47,138.26 160.01,135.72 160.01,109.06
N$174
  Bottom 0.61: IC401.18 104.13,86.83 102.23,88.73 R409.1
N$175
  Bottom 0.61: IC301.3 141.6,125.88 145.41,129.69 145.41,133.66 149.22,137.47 R313.2
N$176
  Bottom 0.61: IC401.10 125.72,84.92 128.27,87.47 R404.1
N$177
  Bottom 0.61: IC401.11 121.91,86.2 123.82,88.1 R405.1
N$178
  Bottom 0.61: IC401.12 R406.1
N$179
  Bottom 0.61: IC401.13 116.83,86.45 115.56,87.72 R407.1
N$180
  Bottom 0.61: R404.2 126.99,96.36 123.19,100.17 RN401.1 123.19,101.44 120.64,104.61 RN402.2
N$181
  Bottom 0.61: R405.2 123.82,96.99 120.64,100.17 RN401.2 120.64,101.44 118.1,104.61 RN402.3
N$182
  Bottom 0.61: R406.2 119.38,97.62 118.1,98.9 RN401.3
N$183
  Bottom 0.61: Q802.1 170.81,35.39 178.43,43.01 178.43,54.45 177.16,55.71 174.62,55.71 173.35,56.98 173.35,69.69 174.62,70.95 K1.2
N$184
  Bottom 0.61: R408.2 149.22,105.25 148.59,105.88 C403.2 144.14,105.88 139.69,101.44 136.52,101.44 133.34,98.9 130.81,98.9 128.9,101.44 128.9,106.52 127.63,107.79 113.02,107.79 111.75,106.52 111.75,103.34 113.02,102.07 RN401.5
N$185
  Bottom 0.61: R409.2 109.85,106.52 110.48,105.88 RN402.6 RN401.6
N$186
  Bottom 0.61: VR401.1 147.31,56.35 150.49,59.52 C404.1 157.47,65.24 158.11,66.13 160.65,66.13 162.17,67.15 162.17,70.95 160.27,72.61 158.36,72.61 157.47,73.5 157.47,74.13 | 157.47,74.13 R412.2 | 157.47,74.13 157.47,78.58 | 157.47,78.58 157.47,83.66 VR402.1 | 157.47,78.58 R411.1
N$187
  Bottom 0.61: R424.2 133.98,60.16 | 133.98,60.16 133.98,62.7 133.34,63.33 IC404.1 | 133.98,60.16 R423.1
N$188
  Bottom 0.61: VR401.3 158.75,46.19 159.38,46.82 159.38,50 158.11,51.27 150.49,51.27 149.22,52.54 149.22,55.71 150.49,56.98 158.11,56.98 159.38,58.25 R413.2
N$189
  Bottom 0.61: R421.1 150.49,69.05 146.68,63.97 144.78,63.97 | 144.78,63.97 136.52,63.97 135.88,64.61 IC404.2 | 144.78,63.97 R423.2
N$190
  Top 0.61: R413.1 150.49,64.61 147.31,68.42 129.53,68.42 128.27,67.15 128.27,65.24 126.99,63.97 124.45,63.97 122.55,62.7 122.55,53.17 120.64,50.63 116.83,50.63 C407.1
  Bottom 0.61: C408.1 158.11,100.8 158.75,100.17 VR402.2 157.47,90.01 156.2,88.73 156.2,79.21 152.78,75.78 150.87,75.78 150.11,74.77 150.11,72.86 151.12,71.59 159.38,71.59 160.9,70.32 160.9,67.78 160.27,67.4 157.73,67.4 154.94,64.61 R413.1
N$191
  Bottom 0.61: R420.1 146.04,86.2 147.31,87.47 VR402.3
N$193
  Bottom 0.61: R802.1 163.82,2.85 162.87,1.9 151.44,1.9 150.49,2.85 CON1.12
N$194
  Bottom 0.61: C411.1 133.34,48.09 133.98,48.73 | 133.98,48.73 R424.1 | C412.2 156.84,48.73 153.03,48.73 C410.1 133.98,48.73
N$195
  Top 0.61: K1.8 K1.7 172.08,58.25 172.08,23.96 168.27,20.16 168.27,4.92 169.54,3.65 R802.2
  Bottom 0.61: K1.8 185.41,58.25 L603.1
N$197
  Bottom 0.61: R421.2 157.86,70.57 150.24,70.57 148.84,72.23 148.84,75.4 150.49,77.05 152.39,77.05 153.66,78.58 153.66,102.7 154.94,103.98 157.47,103.98 158.75,105.25 158.75,106.52 157.47,107.79 144.14,107.79 139.06,102.7 135.88,102.7 133.34,100.8 C409.1
N$198
  Bottom 0.61: 132.07,107.15 C409.2 | 132.07,107.15 128.27,110.96 109.85,110.96 105.41,115.41 105.41,117.31 101.91,120.8 101.91,124.3 111.12,133.5 VR301.3 | 132.07,107.15 R422.1
V+  (via drill 0.61)
  Top 0.61: IC251.8 46.03,81.12 43.18,83.97 43.18,85.88 42.22,86.83 38.73,86.83 37.78,85.88 35.24,85.88 IC203.IN | v48.26,77.98 58.49,77.98 61.59,81.08 IC253.IN
  Top 0.813: IC701.OUT 55.24,18.89 56.51,17.62 78.73,17.62 85.72,10.63 109.85,10.63 112.39,8.09 127.63,8.09 129.22,6.5 132.55,6.5 133.98,8.09 137.79,8.09 | 137.79,8.09 140.19,8.09 | CON1.1 CON1.2 CON1.4 CON1.3 | CON1.1 CON1.3 | 140.19,8.09 140.3,8.09 140.33,8.12 CON1.3 | 140.19,8.09 R505.1 | 137.79,8.09 CON1.1 | 140.19,8.09 140.97,8.09 145.66,12.79 145.66,18.5 146.68,19.52 146.68,25.23 150.49,29.05 IC501.7 | IC202.8 67.94,56.98 56.51,45.55 56.51,27.78 C702.1
  Bottom 0.61: IC203.IN 34.29,85.56 34.29,80.48 31.74,77.94 21.27,77.94 19.68,79.53 IC201.8 | R411.2 149.85,78.58 147.57,76.04 147.57,72.23 146.04,70.95 134.62,70.95 133.34,72.23 IC404.8 133.34,74.13 135.88,76.67 135.88,86.2 147.95,97.62 147.95,101.44 146.68,102.7 145.41,102.7 131.28,89.97 131.28,86.8 132.07,86.01 132.07,82.39 131.44,81.75 117.47,81.75 115.56,83.66 115.56,86.2 114.93,86.83 113.66,86.83 113.02,86.2 113.02,83.66 111.12,81.75 102.86,81.75 98.74,85.88 61.59,85.88 | IC501.7 152.87,29.05 153.03,29.2 173.35,29.2 174.46,30.32 IC601.IN | IC251.8 46.35,79.89 v48.26,77.98
  Bottom 0.813: 55.24,23.96 C702.1 | 55.24,23.96 IC701.OUT | 55.24,23.96 C701.1 34.92,23.96 33.65,22.7 IC702.IN | 61.59,81.12 61.59,85.88 IC253.IN | 61.59,81.12 65.4,81.12 66.67,79.84 IC252.8 | 61.59,81.12 61.59,72.86 62.86,71.59 62.86,67.78 64.13,66.51 66.35,66.51 67.3,65.56 67.3,58.89 69.21,56.98 IC202.8

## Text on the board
Top: TOP | FM CCIR TRX | MAINBOARD v1.05 | (c)2010 ACE Ltd. Inc
Bottom: BOTTOM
